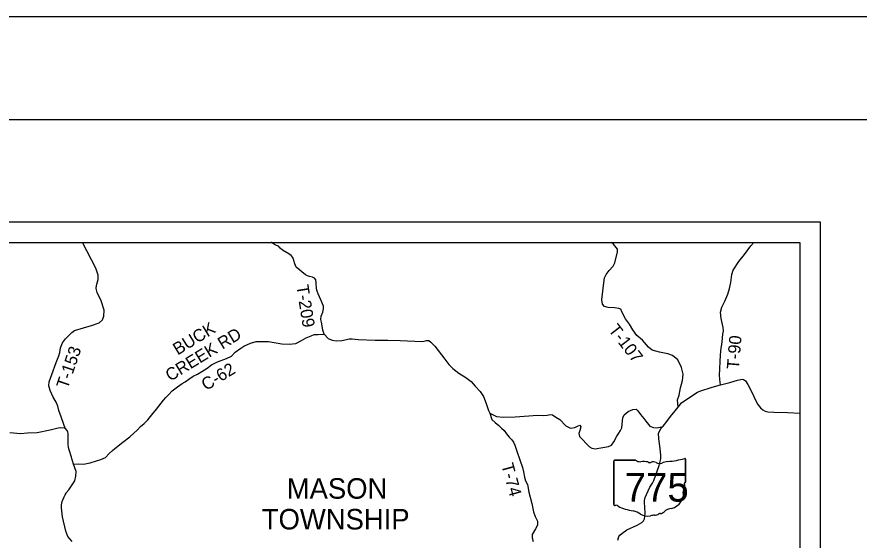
# Model space of a CAD drawing. Extents: x 0 to 34, y 0 to 22.
# Drawn here: x 5.084 to 9.19, y 19.448 to 22 of the extents above; entities that cross this region are included whole.
import ezdxf

# ---------------------------------------------------------------- set-up
doc = ezdxf.new("R2010")
doc.units = 0
for name, color, linetype in [('GM_X_County_Road', 7, 'Continuous'), ('GM_X_County_Road_Text', 7, 'Continuous'), ('GM_X_State_Route', 7, 'Continuous'), ('GM_X_State_Shield', 7, 'Continuous'), ('GM_X_Township_Road', 7, 'Continuous'), ('GM_X_Township_Road_Text', 7, 'Continuous'), ('GM_X_Township_Text', 7, 'Continuous'), ('SH_Border', 7, 'Continuous'), ('SH_Cut_Line', 7, 'Continuous'), ('SH_Data', 7, 'Continuous'), ('SH_Masking', 7, 'Continuous')]:
    doc.layers.add(name, color=color, linetype=linetype)

msp = doc.modelspace()

# ---------------------------------------------------------------- linework, layer by layer
at = {"layer": 'GM_X_County_Road'}
for points in [[(6.176, 20.3834), (6.1761, 20.3834), (6.1906, 20.3938), (6.2224, 20.4087), (6.2511, 20.4172), (6.2769, 20.4166), (6.3102, 20.4164), (6.3383, 20.4123), (6.3747, 20.406), (6.4107, 20.4039), (6.4433, 20.4075), (6.4716, 20.4217), (6.4943, 20.434), (6.5181, 20.4451), (6.5329, 20.4509), (6.5522, 20.4506), (6.5825, 20.4519), (6.6008, 20.4311), (6.6213, 20.4232), (6.6418, 20.4203), (6.6672, 20.4208), (6.6914, 20.4258), (6.7035, 20.4297), (6.7191, 20.4298), (6.7471, 20.4269), (6.8298, 20.4238), (6.8916, 20.423), (6.9526, 20.421), (7.0231, 20.4187), (7.0553, 20.4166), (7.0689, 20.4182), (7.0814, 20.4216), (7.092, 20.4217), (7.1023, 20.4134), (7.1214, 20.3934), (7.1694, 20.3302)], [(5.3598, 19.8192), (5.3836, 19.8194), (5.4083, 19.8191), (5.442, 19.8257), (5.4726, 19.8339), (5.4931, 19.8408), (5.5154, 19.8504), (5.5342, 19.8699), (5.5504, 19.8851), (5.5613, 19.8943), (5.6006, 19.9264), (5.6338, 19.9512), (5.6722, 19.9864), (5.6873, 20.002), (5.7047, 20.0161), (5.7231, 20.0341), (5.7415, 20.0592), (5.7641, 20.0859), (5.7984, 20.1298), (5.8108, 20.1435), (5.8236, 20.1569), (5.8417, 20.1759), (5.8673, 20.1962), (5.89, 20.2123), (5.9047, 20.2196), (5.9228, 20.2329), (5.944, 20.2471), (5.9651, 20.2574), (5.9848, 20.2708), (6.0108, 20.2869), (6.0323, 20.3022), (6.0622, 20.3172), (6.1064, 20.3333), (6.1295, 20.3445), (6.1487, 20.3639), (6.176, 20.3834)], [(7.1694, 20.3302), (7.1695, 20.3301), (7.189, 20.3044), (7.192, 20.3015), (7.2096, 20.2848), (7.2381, 20.2629), (7.2716, 20.2418), (7.2986, 20.221), (7.3184, 20.1995), (7.3417, 20.1726), (7.3593, 20.1488), (7.3716, 20.115), (7.3835, 20.0798), (7.3897, 20.0676)], [(7.3897, 20.0676), (7.4216, 20.0507), (7.4554, 20.0482), (7.5133, 20.0489), (7.58, 20.0537), (7.6224, 20.0566), (7.652, 20.0552), (7.6687, 20.058), (7.6846, 20.0607), (7.6948, 20.0589), (7.7119, 20.0483), (7.7306, 20.0366), (7.7592, 20.0049), (7.7831, 19.994), (7.8032, 19.9967), (7.8202, 20.0059), (7.8274, 20.0094), (7.8323, 20.0003), (7.8283, 19.9832), (7.8231, 19.9683), (7.8269, 19.9528), (7.8753, 19.9036), (7.886, 19.8965), (7.9023, 19.8939), (7.9686, 19.9045), (7.9826, 19.9106), (7.9946, 19.9266), (8.0088, 19.9548), (8.0175, 19.9689), (8.0257, 19.9822), (8.0336, 19.9952), (8.035, 20.0134), (8.0375, 20.0449), (8.0446, 20.0586), (8.0631, 20.0754), (8.0858, 20.0858), (8.1021, 20.0859), (8.1116, 20.0783), (8.1242, 20.0609), (8.1402, 20.0405), (8.1494, 20.0276), (8.1696, 20.0045), (8.1867, 19.9978), (8.2015, 19.9956), (8.2291, 19.9998)]]:
    msp.add_lwpolyline(points, dxfattribs=at)
at = {"layer": 'GM_X_State_Route'}
for points in [[(8.014, 19.4471), (8.0188, 19.4653), (8.0231, 19.4728), (8.0331, 19.481), (8.0579, 19.4977), (8.1083, 19.5209), (8.1301, 19.5342), (8.139, 19.5417), (8.1433, 19.5515), (8.1459, 19.5777), (8.1445, 19.6107), (8.1433, 19.6293), (8.1434, 19.6415), (8.1471, 19.6566), (8.1616, 19.6891), (8.169, 19.706), (8.1822, 19.7252), (8.1892, 19.738), (8.2146, 19.8124), (8.2205, 19.8309), (8.2226, 19.8438), (8.2232, 19.8609), (8.2199, 19.8947), (8.213, 19.9423), (8.2115, 19.9696), (8.2229, 19.9915), (8.2291, 19.9998), (8.234, 20.0031), (8.2529, 20.0259), (8.2703, 20.0504), (8.2927, 20.0785), (8.307, 20.097), (8.3236, 20.1168), (8.3638, 20.1447), (8.4025, 20.1703), (8.4124, 20.1747), (8.4737, 20.1943), (8.5133, 20.2051), (8.5594, 20.2169), (8.5974, 20.2278), (8.6127, 20.2317), (8.6195, 20.2328), (8.6259, 20.2319), (8.6353, 20.2253), (8.6468, 20.2073), (8.6663, 20.1694), (8.6866, 20.127), (8.6962, 20.1086), (8.7085, 20.0929), (8.7201, 20.0832), (8.7313, 20.077), (8.7449, 20.0737), (8.7737, 20.0725), (8.8401, 20.0712), (8.9, 20.067)], [(5.3515, 19.8467), (5.3499, 19.8532), (5.3386, 19.8876), (5.3354, 19.9002), (5.3341, 19.9165), (5.3336, 19.9605), (5.3334, 19.9685), (5.3316, 19.9746), (5.3283, 19.9823), (5.3193, 19.9942), (5.3148, 19.9946), (5.2985, 19.9952), (5.2852, 19.9947), (5.2468, 19.9842), (5.1822, 19.9715), (5.1351, 19.9688), (5.101, 19.9666), (5.0495, 19.9712)], [(5.3241, 19.6767), (5.325, 19.6782), (5.3377, 19.6932), (5.3672, 19.7372), (5.372, 19.7591), (5.3724, 19.7827), (5.3598, 19.8192), (5.3545, 19.8346), (5.3515, 19.8467)], [(5.3537, 19.4409), (5.3414, 19.4536), (5.3329, 19.4663), (5.3223, 19.4922), (5.3066, 19.5608), (5.3008, 19.6057), (5.301, 19.6201), (5.3039, 19.6356), (5.3145, 19.659), (5.3195, 19.6682), (5.3241, 19.6767)]]:
    msp.add_lwpolyline(points, dxfattribs=at)
at = {"layer": 'GM_X_State_Shield'}
for p, q in [((7.9936, 19.8336), (7.9936, 19.621)), ((8.0996, 19.8372), (7.9971, 19.8372)), ((8.3437, 19.7313), (8.3437, 19.8425)), ((8.3437, 19.7313), (8.3437, 19.7313))]:
    msp.add_line(p, q, dxfattribs=at)
for centre, major_axis, start_param, end_param in [((7.9976, 19.834), (0.00406, 0), 1.712693, 3.28349), ((8.124, 19.8619), (0.0393, 0), 4.042523, 4.731795), ((8.2664, 19.7723), (0.0747, 0), 1.699011, 2.107814), ((8.219, 20.1271), (0.3713, 0), 4.814394, 5.042369), ((8.3398, 19.843), (0.0039, 0), 6.141152, 7.989035), ((8.1371, 19.7179), (0.1412, 0), 1.404758, 1.657858), ((8.1691, 19.8351), (0.0113, 0), 3.836095, 5.185415), ((8.1858, 19.8106), (0.0236, 0), 0.950623, 2.079405), ((8.2162, 19.8443), (0.0284, 0), 4.081561, 5.145723), ((8.3428, 19.7232), (0.00603, 0), 1.883978, 3.671073), ((8.3045, 19.7091), (0.0362, 0), 5.934695, 6.695948), ((8.3396, 19.7309), (0.00417, 0), 5.05454, 6.418171), ((8.2398, 19.6706), (0.0929, 0), 5.101752, 6.440018), ((8.3577, 19.6848), (0.0263, 0), 2.387724, 3.262537), ((7.9977, 19.6206), (0.00409, 0), 3.00124, 4.508301), ((7.9983, 19.6423), (0.0312, 0), 4.665946, 4.897461), ((8.0047, 19.6088), (0.0113, 0), 0.519207, 1.627899), ((8.1468, 19.7997), (0.2681, 0), 4.195997, 4.488961), ((8.0669, 19.5255), (0.0839, 0), 0.823519, 1.323587), ((8.2145, 19.6004), (0.03, 0), 4.937069, 5.64225), ((8.279, 19.5613), (0.0509, 0), 1.647645, 2.488434), ((8.1576, 19.6077), (0.0532, 0), 4.026481, 4.996735), ((8.1884, 19.5342), (0.0437, 0), 1.495662, 1.94098), ((8.1923, 19.5918), (0.0284, 0), 4.691044, 5.507374), ((8.2179, 19.5712), (0.00798, 0), 1.147584, 2.315152)]:
    msp.add_ellipse(centre, major_axis=major_axis, ratio=0.8, start_param=start_param, end_param=end_param, dxfattribs=at)
at = {"layer": 'GM_X_Township_Road'}
for points in [[(5.4706, 20.6759), (5.4706, 20.6761), (5.4702, 20.6781), (5.4729, 20.6963), (5.4794, 20.7195), (5.4798, 20.74), (5.4692, 20.7746), (5.4034, 20.9)], [(6.5825, 20.4519), (6.5748, 20.4725), (6.5726, 20.493), (6.5688, 20.5105), (6.5662, 20.5238), (6.567, 20.5394), (6.5746, 20.5603), (6.5792, 20.5766), (6.5789, 20.5884), (6.5664, 20.62), (6.5521, 20.6485), (6.5472, 20.6626), (6.5442, 20.674), (6.5431, 20.7025), (6.5405, 20.7166), (6.5352, 20.7261), (6.5245, 20.731), (6.5101, 20.733), (6.5007, 20.7372), (6.4908, 20.7425), (6.4461, 20.7799), (6.4382, 20.7947), (6.4344, 20.8122), (6.4284, 20.8263), (6.4208, 20.8362), (6.4091, 20.8434), (6.3784, 20.8614), (6.3674, 20.872), (6.3598, 20.8812), (6.3492, 20.8854), (6.3393, 20.8892), (6.3249, 20.8991), (6.3242, 20.9)], [(8.307, 20.097), (8.3049, 20.132), (8.3116, 20.1556), (8.3194, 20.1906), (8.329, 20.226), (8.3311, 20.2575), (8.3245, 20.2894), (8.3065, 20.3269), (8.2806, 20.3488), (8.2578, 20.3563), (8.2161, 20.3641), (8.1815, 20.3738), (8.1629, 20.3889), (8.1335, 20.4233), (8.1057, 20.4456), (8.087, 20.4736), (8.0705, 20.5016), (8.0506, 20.5277), (8.033, 20.5611), (8.0273, 20.5736), (8.0189, 20.5781), (7.9969, 20.5807), (7.9666, 20.5828), (7.9476, 20.5869), (7.9384, 20.5982), (7.9357, 20.6202), (7.9423, 20.6765), (7.9483, 20.7267), (7.9558, 20.7442), (7.9716, 20.7632), (7.9904, 20.7835), (7.9987, 20.7995), (8.0116, 20.8534), (8.0119, 20.8675), (7.9928, 20.8913), (7.9823, 20.9)], [(8.5133, 20.2051), (8.5105, 20.2307), (8.5094, 20.2535), (8.5099, 20.2809), (8.5122, 20.3223), (8.5158, 20.3709), (8.5216, 20.4157), (8.5255, 20.4518), (8.5285, 20.4693), (8.5271, 20.4849), (8.5169, 20.5286), (8.5136, 20.5598), (8.5205, 20.5845), (8.5357, 20.6137), (8.5491, 20.6471), (8.5579, 20.6748), (8.5644, 20.7037), (8.569, 20.7428), (8.5751, 20.7649), (8.6037, 20.8066), (8.6303, 20.8411), (8.6616, 20.8824), (8.6757, 20.9)], [(5.3193, 19.9942), (5.3126, 20.0123), (5.3002, 20.0499), (5.2892, 20.08), (5.2836, 20.102), (5.2761, 20.1207), (5.2606, 20.1458), (5.2458, 20.1777), (5.2394, 20.2006), (5.241, 20.2196), (5.2547, 20.2564), (5.2761, 20.3149), (5.2884, 20.3471), (5.2941, 20.3631), (5.2972, 20.3851), (5.3063, 20.4094), (5.3208, 20.4291), (5.3345, 20.4428), (5.3512, 20.4598), (5.3649, 20.4701), (5.4094, 20.4829), (5.4481, 20.4946), (5.4853, 20.5074), (5.5009, 20.5218), (5.5085, 20.54), (5.5101, 20.5689), (5.4947, 20.6153), (5.4747, 20.656), (5.472, 20.669), (5.4706, 20.6759)], [(7.3897, 20.0676), (7.399, 20.0358), (7.4146, 20.021), (7.4325, 20.0075), (7.4462, 19.9935), (7.4595, 19.9825), (7.4699, 19.9662), (7.484, 19.95), (7.4962, 19.9375), (7.5046, 19.925), (7.5115, 19.9114), (7.5207, 19.8818), (7.5358, 19.8397), (7.5481, 19.8014), (7.5535, 19.7809), (7.559, 19.7555), (7.5636, 19.7373), (7.5728, 19.7187), (7.5799, 19.6823), (7.5938, 19.6262), (7.602, 19.5856), (7.6097, 19.5632), (7.6212, 19.5412), (7.6225, 19.5211), (7.6124, 19.5032), (7.5962, 19.475), (7.5956, 19.4591), (7.6013, 19.4416)]]:
    msp.add_lwpolyline(points, dxfattribs=at)
at = {"layer": 'SH_Border'}
msp.add_lwpolyline([(1.5, 21.5), (33.5, 21.5), (33.5, 0.5), (1.5, 0.5)], close=True, dxfattribs=at)
at = {"layer": 'SH_Cut_Line'}
msp.add_lwpolyline([(0, 0), (34, 0), (34, 22), (0, 22)], close=True, dxfattribs=at)
at = {"layer": 'SH_Data'}
for p, q in [((2, 21), (9, 21)), ((9, 21), (9, 14)), ((2.1, 20.9), (8.9, 20.9)), ((8.9, 20.9), (8.9, 14.1))]:
    msp.add_line(p, q, dxfattribs=at)
at = {"layer": 'SH_Masking'}
for p, q in [((7.9936, 19.621), (7.9936, 19.8336)), ((7.9971, 19.8373), (8.0996, 19.8373)), ((8.3437, 19.8425), (8.3437, 19.7313)), ((8.341, 19.7277), (8.341, 19.7277))]:
    msp.add_line(p, q, dxfattribs=at)
for centre, major_axis, start_param, end_param in [((7.9976, 19.834), (0.00406, 0), 1.712693, 3.28349), ((8.124, 19.8619), (0.0393, 0), 4.042523, 4.731795), ((8.2664, 19.7723), (0.0747, 0), 1.699011, 2.107814), ((8.219, 20.1271), (0.3713, 0), 4.814394, 5.042369), ((8.3398, 19.843), (0.0039, 0), 6.141152, 7.989035), ((8.1371, 19.7179), (0.1412, 0), 1.404758, 1.657858), ((8.1691, 19.8351), (0.0113, 0), 3.836095, 5.185415), ((8.1858, 19.8106), (0.0236, 0), 0.950623, 2.079405), ((8.2162, 19.8443), (0.0284, 0), 4.081561, 5.145723), ((8.3428, 19.7232), (0.00603, 0), 1.883978, 3.671073), ((8.3045, 19.7091), (0.0362, 0), 5.934695, 6.695948), ((8.3396, 19.7309), (0.00417, 0), 5.05454, 6.418171), ((8.2398, 19.6706), (0.0929, 0), 5.101752, 6.440018), ((8.3577, 19.6848), (0.0263, 0), 2.387724, 3.262537), ((7.9977, 19.6206), (0.00409, 0), 3.00124, 4.508301), ((7.9983, 19.6423), (0.0312, 0), 4.665946, 4.897461), ((8.0047, 19.6088), (0.0113, 0), 0.519207, 1.627899), ((8.1468, 19.7997), (0.2681, 0), 4.195997, 4.488961), ((8.0669, 19.5255), (0.0839, 0), 0.823519, 1.323587), ((8.2145, 19.6004), (0.03, 0), 4.937069, 5.64225), ((8.279, 19.5613), (0.0509, 0), 1.647645, 2.488434), ((8.1576, 19.6077), (0.0532, 0), 4.026481, 4.996735), ((8.1884, 19.5342), (0.0437, 0), 1.495662, 1.94098), ((8.1923, 19.5918), (0.0284, 0), 4.691044, 5.507374), ((8.2179, 19.5712), (0.00798, 0), 1.147584, 2.315152)]:
    msp.add_ellipse(centre, major_axis=major_axis, ratio=0.8, start_param=start_param, end_param=end_param, dxfattribs=at)

# ---------------------------------------------------------------- texts
at = {"layer": 'GM_X_County_Road_Text'}
for s, p in [('BUCK', (5.8678, 20.3481)), ('CREEK RD', (5.8312, 20.2202)), ('C-62', (6.0063, 20.1749))]:
    msp.add_text(s, height=0.06, rotation=31.4456, dxfattribs=at).set_placement(p)
at = {"layer": 'GM_X_State_Shield'}
msp.add_text('775', height=0.14004, dxfattribs=at).set_placement((8.0467, 19.636))
at = {"layer": 'GM_X_Township_Road_Text'}
for s, rotation, p in [('T-209', 278.9255, (6.4456, 20.6886)), ('T-107', 307.669, (7.9648, 20.4727)), ('T-90', 85.3803, (8.6037, 20.2794)), ('T-153', 71.0094, (5.331, 20.1822)), ('T-74', 285.4163, (7.4442, 19.8145))]:
    msp.add_text(s, height=0.06, rotation=rotation, dxfattribs=at).set_placement(p)
at = {"layer": 'GM_X_Township_Text'}
for s, p in [('MASON', (6.3995, 19.65)), ('TOWNSHIP', (6.2778, 19.5))]:
    msp.add_text(s, height=0.1, dxfattribs=at).set_placement(p)

doc.saveas('drawing.dxf')
